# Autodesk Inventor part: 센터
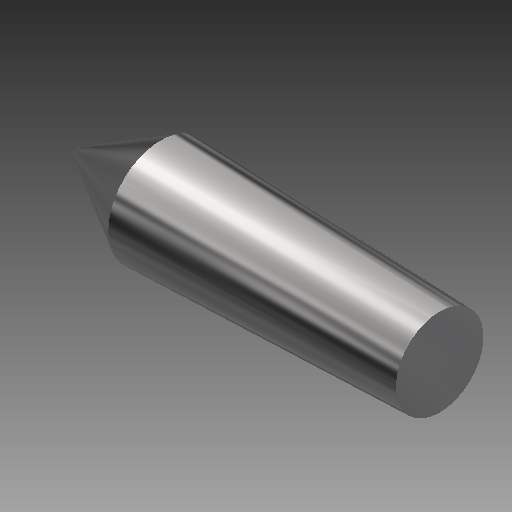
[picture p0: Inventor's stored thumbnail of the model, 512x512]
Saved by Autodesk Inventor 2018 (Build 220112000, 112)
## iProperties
Created: 2019-10
Part Number: 센터
Material: 스테인리스강
Document SubType Name: Modeling
Designer: mduedu
Density: 1 g/cm^3
Appearance: 반광택
Author: mduedu
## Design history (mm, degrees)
sketch "스케치1"
  geometry: L1 (0, 0)-(-31.5, 0); L2 (-31.5, 0)-(-31.5, -0.125); L3 (-31.5, -0.125)-(-23.922, -4.5); L4 (-23.922, -4.5)-(0, -3.751); L5 (0, -3.751)-(0, 0)
  constraints: 10 end point, 1 horizontal, 1 parallel, 1 perpendicular
  dimensions: "d0" = 31.5 distance of L1.start L1.end; "d1" = 7.502 diameter of L4.end L1; "d2" = 30 deg angle of L1 L3; "d3" = 7.578 horizontal distance of L2.end L3.end; "d5" = 0.25 diameter of L2.end L1; "d6" = 23.922 horizontal distance of L3.end L4.end (derived); "d7" = 9.00032 diameter of L3.end L1 (derived)
revolve "회전1" sketch "스케치1" stored, may be unused: angle "d8" = 90 deg
node "솔리드1"
